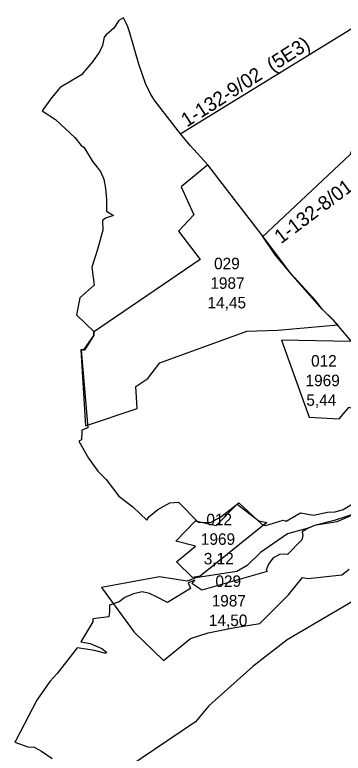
# Model space of a CAD drawing. Extents: x -557103 to -548162, y -1041918 to -1033974.
# Drawn here: x -554621 to -553807, y -1037353 to -1035524 of the extents above; entities that cross this region are included whole.
import ezdxf

# ---------------------------------------------------------------- set-up
doc = ezdxf.new("R2010")
doc.units = 0
for name, color, linetype in [('body3', 7, 'Continuous'), ('Vrstva 12', 7, 'Continuous'), ('Vrstva 13', 7, 'Continuous'), ('Vrstva 16', 7, 'Continuous'), ('Vrstva 9', 7, 'Continuous')]:
    doc.layers.add(name, color=color, linetype=linetype)

msp = doc.modelspace()

# ---------------------------------------------------------------- linework, layer by layer
at = {"layer": 'body3'}
for p, q in [((-554351.4, -1035531.2), (-554363.3, -1035537.8)), ((-554344.9, -1035544.6), (-554351.4, -1035531.2)), ((-554363.3, -1035537.8), (-554375.7, -1035556.8)), ((-554340.8, -1035554.2), (-554344.9, -1035544.6)), ((-554375.7, -1035556.8), (-554394.6, -1035573.5)), ((-554337.1, -1035566.1), (-554340.8, -1035554.2)), ((-554313.6, -1035646), (-554337.1, -1035566.1)), ((-554399.2, -1035579.2), (-554403.5, -1035600.1)), ((-554394.6, -1035573.5), (-554399.2, -1035579.2)), ((-554403.5, -1035600.1), (-554411.1, -1035616)), ((-554411.1, -1035616), (-554428.3, -1035640.7)), ((-554428.3, -1035640.7), (-554455.4, -1035672.4)), ((-554296.8, -1035694.2), (-554313.6, -1035646)), ((-554455.4, -1035672.4), (-554508.3, -1035704.2)), ((-554284.3, -1035721.2), (-554296.8, -1035694.2)), ((-554508.3, -1035704.2), (-554529.8, -1035729.5)), ((-554529.8, -1035729.5), (-554553.1, -1035762)), ((-554273.3, -1035738.2), (-554284.3, -1035721.2)), ((-554210.7, -1035818.6), (-554273.3, -1035738.2)), ((-554553.1, -1035762), (-554550.9, -1035763.6)), ((-554550.9, -1035763.6), (-554520.3, -1035783.1)), ((-554520.3, -1035783.1), (-554472.6, -1035827.6)), ((-554186.4, -1035847.9), (-554210.7, -1035818.6)), ((-554472.6, -1035827.6), (-554456.8, -1035847.5)), ((-554456.8, -1035847.5), (-554449.6, -1035851.8)), ((-554449.6, -1035851.8), (-554428, -1035888)), ((-554142.4, -1035895.9), (-554186.4, -1035847.9)), ((-554428, -1035888), (-554408.5, -1035912)), ((-554098.5, -1035952.8), (-554142.4, -1035895.9)), ((-554408.5, -1035912), (-554400.4, -1035931.4)), ((-554400.4, -1035931.4), (-554396.6, -1035954.4)), ((-554396.6, -1035954.4), (-554394.1, -1035981.3)), ((-554010.1, -1036068.4), (-554098.5, -1035952.8)), ((-554394.1, -1035981.3), (-554393.9, -1036010.4)), ((-554393.9, -1036010.4), (-554376.7, -1036021)), ((-554395.9, -1036028), (-554403.6, -1036033.8)), ((-554376.7, -1036021), (-554395.9, -1036028)), ((-554403.6, -1036033.8), (-554403.2, -1036057.9)), ((-554403.2, -1036057.9), (-554416.2, -1036105.6)), ((-553975.5, -1036118.3), (-554010.1, -1036068.4)), ((-554416.2, -1036105.6), (-554430.3, -1036148.9)), ((-553936.8, -1036165), (-553975.5, -1036118.3)), ((-554430.3, -1036148.9), (-554424.4, -1036194.1)), ((-553875.5, -1036231.8), (-553936.8, -1036165)), ((-554424.4, -1036194.1), (-554460, -1036225.4)), ((-554460, -1036225.4), (-554468.3, -1036267)), ((-553858.2, -1036254.1), (-553875.5, -1036231.8)), ((-553831.9, -1036279.4), (-553858.2, -1036254.1)), ((-554468.3, -1036267), (-554424.8, -1036309)), ((-553771.5, -1036351), (-553831.9, -1036279.4)), ((-554425.1, -1036317.8), (-554448.6, -1036354.7)), ((-554424.8, -1036309), (-554425.1, -1036317.8)), ((-554448.6, -1036354.7), (-554456.8, -1036354.8)), ((-554456.8, -1036354.8), (-554448.6, -1036451)), ((-554448.6, -1036451), (-554440.4, -1036547.1)), ((-554455.1, -1036556.3), (-554455.5, -1036576.7)), ((-554455, -1036553.4), (-554455.1, -1036556.3)), ((-554440.4, -1036547.1), (-554455, -1036553.4)), ((-554455.5, -1036576.7), (-554462, -1036580.4)), ((-554462, -1036580.4), (-554438.8, -1036622.5)), ((-554438.8, -1036622.5), (-554415.6, -1036654.6)), ((-554415.6, -1036654.6), (-554394.9, -1036675)), ((-554394.9, -1036675), (-554363.6, -1036716.3)), ((-554363.6, -1036716.3), (-554328.9, -1036742.8)), ((-554266.4, -1036749.8), (-554237.1, -1036733.2)), ((-554237.1, -1036733.2), (-554215.1, -1036731.4)), ((-554215.1, -1036731.4), (-554167, -1036781.2)), ((-554110.4, -1036768.1), (-554065.7, -1036732.9)), ((-554065.7, -1036732.9), (-554008.4, -1036787)), ((-553807.4, -1036749.5), (-553776.2, -1036731)), ((-554328.9, -1036742.8), (-554293.6, -1036775.7)), ((-554289, -1036767.9), (-554266.4, -1036749.8)), ((-553948.3, -1036778.3), (-553913.2, -1036757.8)), ((-553913.2, -1036757.8), (-553880.8, -1036764)), ((-553880.8, -1036764), (-553846.3, -1036755.9)), ((-553846.3, -1036755.9), (-553827.3, -1036755.2)), ((-553827.3, -1036755.2), (-553807.4, -1036749.5)), ((-553743.7, -1036745.8), (-553823, -1036780.5)), ((-554293.6, -1036775.7), (-554289, -1036767.9)), ((-554135.9, -1036781.7), (-554110.4, -1036768.1)), ((-553998.6, -1036789.1), (-553956.4, -1036776)), ((-553956.4, -1036776), (-553948.3, -1036778.3)), ((-554167, -1036781.2), (-554135.9, -1036781.7)), ((-554008.4, -1036787), (-553998.6, -1036789.1)), ((-553893.8, -1036796.1), (-553909, -1036805.3)), ((-553878.4, -1036789.4), (-553893.8, -1036796.1)), ((-553823, -1036780.5), (-553878.4, -1036789.4)), ((-553906.9, -1036813.7), (-553909.9, -1036824.6)), ((-553909, -1036805.3), (-553906.9, -1036813.7)), ((-553909.9, -1036824.6), (-553945.6, -1036860.9)), ((-553981.6, -1036869.8), (-553992.2, -1036884.8)), ((-553964.7, -1036861), (-553981.6, -1036869.8)), ((-553953.5, -1036859.9), (-553964.7, -1036861)), ((-553945.6, -1036860.9), (-553953.5, -1036859.9)), ((-553992.2, -1036884.8), (-553998.3, -1036900.3)), ((-553995.6, -1036903), (-554157.6, -1036949.5)), ((-553998.3, -1036900.3), (-553995.6, -1036903)), ((-554174.5, -1036924.7), (-554191.5, -1036931.2)), ((-554178.9, -1036930), (-554174.5, -1036924.7)), ((-554191.5, -1036931.2), (-554185.8, -1036945.3)), ((-554182.1, -1036933.3), (-554178.9, -1036930)), ((-554157.6, -1036949.5), (-554182.1, -1036933.3)), ((-554327.1, -1036958.2), (-554348, -1036967.3)), ((-554305.1, -1036954), (-554327.1, -1036958.2)), ((-554287, -1036958.1), (-554305.1, -1036954)), ((-554270, -1036966.2), (-554287, -1036958.1)), ((-554185.8, -1036945.3), (-554242.6, -1036979.9)), ((-554362.8, -1036978.3), (-554386.6, -1036986.8)), ((-554348, -1036967.3), (-554362.8, -1036978.3)), ((-554242.6, -1036979.9), (-554270, -1036966.2)), ((-554386.6, -1036986.8), (-554386.6, -1037002.7)), ((-554387.9, -1037015.3), (-554427.6, -1037020.8)), ((-554386.6, -1037002.7), (-554387.9, -1037015.3)), ((-554427.9, -1037027.6), (-554457.6, -1037077.1)), ((-554427.6, -1037020.8), (-554427.9, -1037027.6)), ((-554457.6, -1037077.1), (-554434.5, -1037081.7)), ((-554434.5, -1037081.7), (-554405.2, -1037094.1)), ((-554466.3, -1037092.7), (-554516.1, -1037155.6)), ((-554444, -1037095.5), (-554466.3, -1037092.7)), ((-554423.6, -1037099.3), (-554444, -1037095.5)), ((-554395.1, -1037106.3), (-554423.6, -1037099.3)), ((-554405.2, -1037094.1), (-554394, -1037103)), ((-554394, -1037103), (-554395.1, -1037106.3)), ((-554516.1, -1037155.6), (-554533.8, -1037176.1)), ((-554533.8, -1037176.1), (-554566.7, -1037222.1)), ((-554566.7, -1037222.1), (-554618.8, -1037322.1)), ((-554618.8, -1037322.1), (-554621.1, -1037326.4)), ((-554621.1, -1037326.4), (-554589, -1037337.4)), ((-554589, -1037337.4), (-554572.9, -1037338.5)), ((-554572.9, -1037338.5), (-554555.1, -1037348)), ((-554555.1, -1037348), (-554528.3, -1037366.9))]:
    msp.add_line(p, q, dxfattribs=at)
at = {"layer": 'Vrstva 12'}
msp.add_lwpolyline([(-554209.3, -1035817.9), (-553650.7, -1035473.7), (-553790.3, -1035869.7), (-554007.5, -1036074.1)], dxfattribs=at)
at = {"layer": 'Vrstva 16'}
msp.add_lwpolyline([(-553009.6, -1035496.7), (-553002.1, -1035544), (-553049.5, -1035622.1), (-553086.8, -1035719.3), (-553126.7, -1035856.4), (-553136.7, -1035986), (-553156.6, -1036068.2), (-553271.2, -1036329.9), (-553326, -1036402.2), (-553438.1, -1036581.7), (-553500.4, -1036678.9), (-553537.8, -1036773.6), (-553654.9, -1036898.3), (-553794.4, -1036983), (-553946.4, -1037072.7), (-554030.9, -1037138.8), (-554140.5, -1037236), (-554172.9, -1037275.9), (-554409.6, -1037435.4)], dxfattribs=at)
at = {"layer": 'Vrstva 9'}
for points in [[(-554426.4, -1036310), (-554426.4, -1036318.7), (-554450.6, -1036354.3), (-554457.1, -1036354), (-554445.8, -1036542.5), (-554318.1, -1036499.4), (-554320.9, -1036445.1), (-554291.4, -1036424.9), (-554262, -1036386.2), (-554045.7, -1036308), (-553969.4, -1036305.2), (-553820.3, -1036292.4), (-553858.2, -1036254.1), (-553936.8, -1036165), (-554010.1, -1036068.4), (-554098.5, -1035952.8), (-554142.4, -1035895.9), (-554208.6, -1035950), (-554177.3, -1036019.9), (-554215.1, -1036060.4), (-554161.7, -1036130.4)], [(-554220.3, -1036879.3), (-554173.2, -1036840.8), (-554221.8, -1036827.9), (-554173.2, -1036777.9), (-554121.8, -1036789.3), (-554070.4, -1036736.5), (-554016.2, -1036777.9), (-553996.2, -1036782.2), (-554161.8, -1036915), (-554180.4, -1036917.9)]]:
    msp.add_lwpolyline(points, close=True, dxfattribs=at)
for points in [[(-553787.5, -1036333.8), (-553960.5, -1036330.1), (-553891.5, -1036520.6), (-553817, -1036525.2), (-553792.1, -1036495.8), (-553665.2, -1036545.5), (-553681.2, -1036641.3), (-553702.9, -1036687.9), (-553719.7, -1036719.8), (-553750.4, -1036742), (-553768.5, -1036756.7)], [(-553768.5, -1036756.7), (-553829.4, -1036776.6), (-553878.4, -1036789.6), (-553893.2, -1036796), (-553903, -1036798), (-553945.6, -1036809.7), (-554012, -1036856.5), (-554045.5, -1036888.6), (-554071.2, -1036902.9), (-554172.6, -1036918.6), (-554193.6, -1036926.8), (-554262.2, -1036916.8), (-554406.4, -1036942.5), (-554324.9, -1037053.9), (-554252.2, -1037123.9), (-554186, -1037069.5), (-554141.8, -1037054.8), (-554075.6, -1037041.9), (-554013.9, -1037031.8), (-553943, -1036960.9), (-553908.1, -1036917.7), (-553894.3, -1036920.4), (-553810.5, -1036911.2), (-553792.1, -1036897.4)]]:
    msp.add_lwpolyline(points, dxfattribs=at)

# ---------------------------------------------------------------- texts
at = {"layer": 'Vrstva 13'}
for s, rotation, p in [('1-132-9/02  (5E3)', 32.742, (-554194.7, -1035803.4)), ('1-132-8/01 (5E4)', 36.877, (-553961.4, -1036092.6))]:
    msp.add_text(s, height=35, rotation=rotation, dxfattribs=at).set_placement(p)
at = {"layer": 'Vrstva 9'}
for s, p in [('029', (-554127.2, -1036154.4)), ('1987', (-554136.4, -1036202.9)), ('14,45', (-554143.4, -1036251.4)), ('012', (-553886.8, -1036395.6)), ('1969', (-553900.5, -1036444.1)), ('5,44', (-553898.6, -1036492.6)), ('012', (-554146.2, -1036788.6)), ('1969', (-554159.9, -1036837.1)), ('3,12', (-554152.7, -1036885.6)), ('029', (-554123.9, -1036941.4)), ('1987', (-554133.1, -1036989.9)), ('14,50', (-554140, -1037038.4))]:
    msp.add_text(s, height=28.5, dxfattribs=at).set_placement(p)

doc.saveas('drawing.dxf')
